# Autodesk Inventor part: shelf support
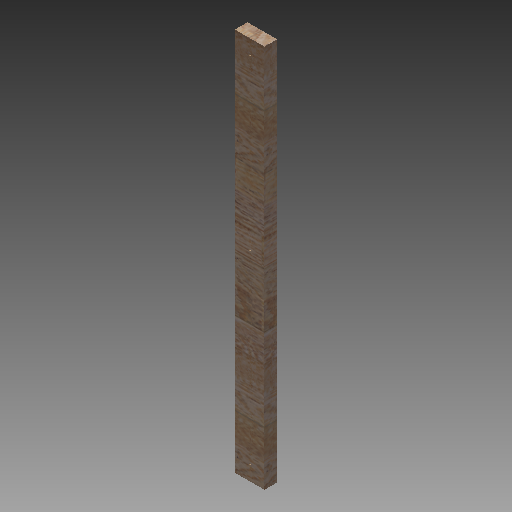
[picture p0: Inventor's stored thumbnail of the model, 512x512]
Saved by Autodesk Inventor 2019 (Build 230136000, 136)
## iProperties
Created: 2013-08
Part Number: shelf support
Material: Generic
Document SubType Name: Modeling
Designer: Patrick Rice
Density: 1 g/cm^3
Appearance: Red Oak - Natural
Author: Patrick Rice
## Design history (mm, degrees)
sketch "Sketch1"
  geometry: L1 (0, 0)-(-88.9, 0); L2 (-88.9, 0)-(-88.9, 38.1); L3 (-88.9, 38.1)-(0, 38.1); L4 (0, 38.1)-(0, 0)
  constraints: 8 end point, 2 parallel, 1 horizontal, 1 perpendicular
  dimensions: "d0" = 88.9 distance of L2.end L3.end; "d1" = 38.1 distance of L1.end L2.end
extrude "Extrusion1" new body sketch "Sketch1" distance "d2" = 1155.7; taper "d3" = 0 deg
hole "Hole1" diameter "d6" = 6.35; stored, may be unused: countersink angle "d10" = 82 deg, drill point angle "d12" = 118 deg; dims "d4" = 44.45, "d5" = 44.45, "d7" = 19.05, "d8" = 9.525, "d9" = 6.35, "d11" = 25.4
hole "Hole2" diameter "d15" = 6.35; stored, may be unused: countersink angle "d19" = 82 deg, drill point angle "d21" = 118 deg; dims "d13" = 603.25, "d14" = 44.45, "d16" = 19.05, "d17" = 9.525, "d18" = 6.35, "d20" = 25.4
hole "Hole3" diameter "d24" = 6.35; stored, may be unused: countersink angle "d28" = 82 deg, drill point angle "d30" = 118 deg; dims "d22" = 44.45, "d23" = 44.45, "d25" = 19.05, "d26" = 9.525, "d27" = 6.35, "d29" = 25.4
body "Solid1"
